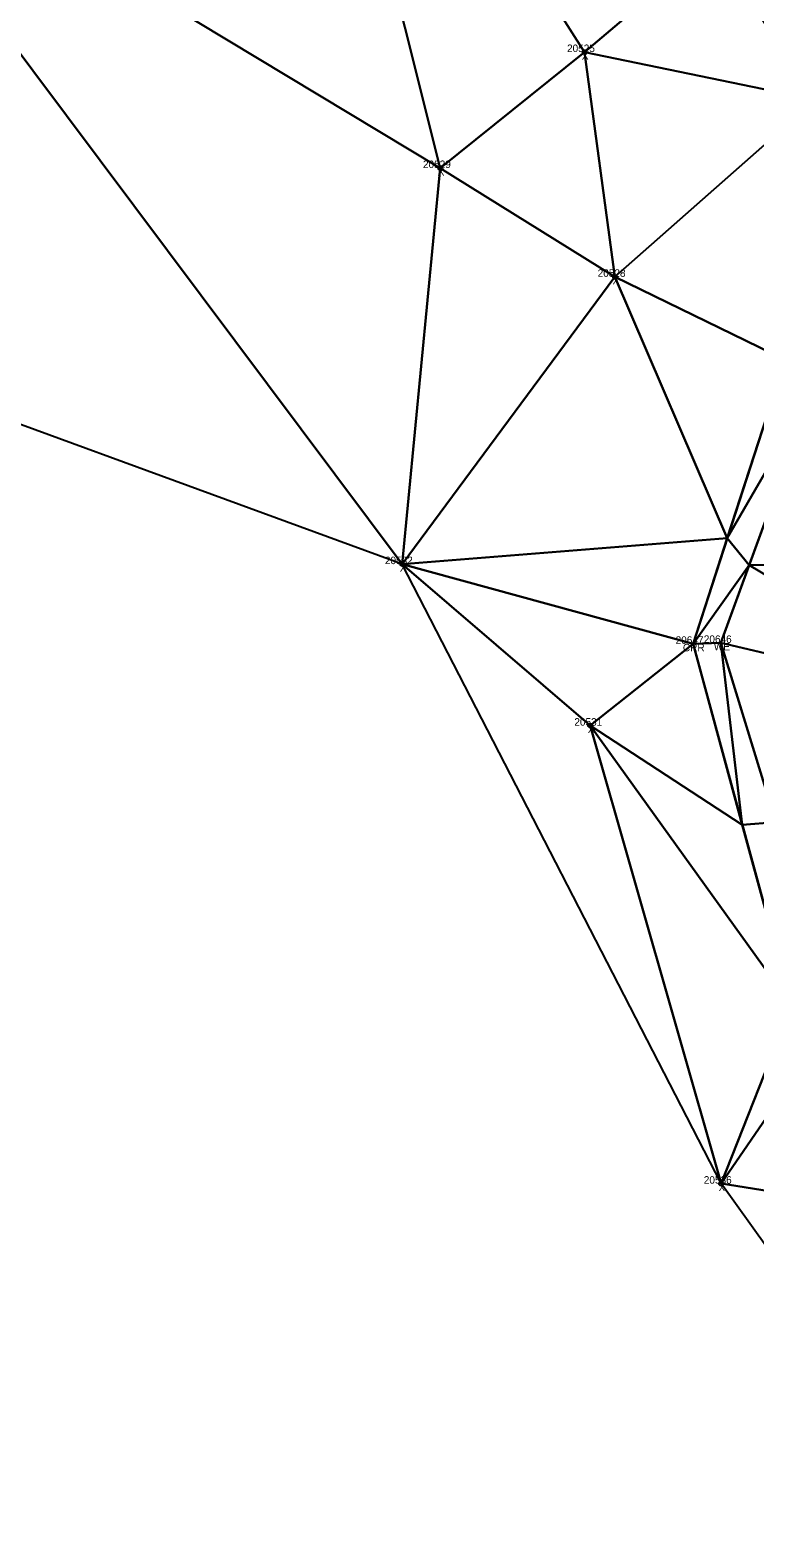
# Model space of a CAD drawing. Extents: x 1966740 to 1969291, y 1117379 to 1118460.
# Drawn here: x 1967626.6 to 1967723.3, y 1117454.2 to 1117655.1 of the extents above; entities that cross this region are included whole.
import ezdxf

# ---------------------------------------------------------------- set-up
doc = ezdxf.new("R2010")
doc.units = 0
for name, color, linetype in [('Level 10', 7, 'Continuous'), ('Level 30', 7, 'Continuous'), ('Level 35', 7, 'Continuous'), ('Level 50', 7, 'Continuous'), ('Level 52', 7, 'Continuous'), ('Level 60', 7, 'Continuous'), ('Level 61', 7, 'Continuous'), ('Level 62', 7, 'Continuous')]:
    doc.layers.add(name, color=color, linetype=linetype)

msp = doc.modelspace()

# ---------------------------------------------------------------- linework, layer by layer
at = {"layer": 'Level 10'}
for points in [[(1967849.83, 1118135.18), (1967825.91, 1118086.77), (1967802.99, 1118041.98), (1967795.15, 1117992.28), (1967793.27, 1117935.35), (1967800.64, 1117889.8), (1967800.4, 1117872.52), (1967800.8, 1117854.99), (1967811.67, 1117837.73), (1967837.15, 1117809.04), (1967808.01, 1117752.12), (1967788.48, 1117706.78), (1967783.36, 1117689.17), (1967764.63, 1117648.93), (1967738.42, 1117613.44), (1967731.11, 1117607.31), (1967718.77, 1117573.47), (1967736.01, 1117517.29), (1967781.71, 1117484.69), (1967799.34, 1117478.73), (1967814.43, 1117469.18)], [(1967794.3, 1117875.45), (1967796.63, 1117853.43), (1967809.67, 1117835.4), (1967828.83, 1117808.28), (1967805.08, 1117754.56), (1967786.33, 1117708.04), (1967780.19, 1117689.35), (1967762.68, 1117651.19), (1967736.39, 1117616.3), (1967727.33, 1117611.21), (1967715.04, 1117573.35), (1967731.01, 1117514.73), (1967775.86, 1117468.11), (1967793.29, 1117458.88), (1967816.39, 1117454.18)]]:
    msp.add_lwpolyline(points, dxfattribs=at)
at = {"layer": 'Level 30'}
for centre in [(1967700.55, 1117652.23), (1967681.31, 1117636.77), (1967704.63, 1117622.27), (1967676.25, 1117583.97), (1967701.31, 1117562.44), (1967718.78, 1117501.39)]:
    msp.add_circle(centre, 0.25, dxfattribs=at)
at = {"layer": 'Level 35'}
for points in [[(1967600.11, 1117685.65), (1967662.45, 1117711.98), (1967681.31, 1117636.77)], [(1967662.45, 1117711.98), (1967717.6, 1117666.66), (1967700.55, 1117652.23)], [(1967662.45, 1117711.98), (1967700.55, 1117652.23), (1967681.31, 1117636.77)], [(1967513.9, 1117643.33), (1967600.11, 1117685.65), (1967676.25, 1117583.97)], [(1967600.11, 1117685.65), (1967681.31, 1117636.77), (1967676.25, 1117583.97)], [(1967700.55, 1117652.23), (1967717.6, 1117666.66), (1967731.36, 1117645.86)], [(1967681.31, 1117636.77), (1967700.55, 1117652.23), (1967704.63, 1117622.27)], [(1967700.55, 1117652.23), (1967731.36, 1117645.86), (1967704.63, 1117622.27)], [(1967704.63, 1117622.27), (1967731.36, 1117645.86), (1967727.33, 1117611.21)], [(1967676.25, 1117583.97), (1967681.31, 1117636.77), (1967704.63, 1117622.27)], [(1967676.25, 1117583.97), (1967704.63, 1117622.27), (1967719.61, 1117587.44)], [(1967704.63, 1117622.27), (1967727.33, 1117611.21), (1967719.61, 1117587.44)], [(1967719.61, 1117587.44), (1967727.33, 1117611.21), (1967731.11, 1117607.31)], [(1967719.61, 1117587.44), (1967731.11, 1117607.31), (1967722.55, 1117583.83)], [(1967722.55, 1117583.83), (1967731.11, 1117607.31), (1967769.03, 1117583.97)], [(1967676.25, 1117583.97), (1967719.61, 1117587.44), (1967715.04, 1117573.35)], [(1967715.04, 1117573.35), (1967719.61, 1117587.44), (1967722.55, 1117583.83)], [(1967676.25, 1117583.97), (1967715.04, 1117573.35), (1967701.31, 1117562.44)], [(1967676.25, 1117583.97), (1967701.31, 1117562.44), (1967718.78, 1117501.39)], [(1967715.04, 1117573.35), (1967722.55, 1117583.83), (1967718.77, 1117573.47)], [(1967718.77, 1117573.47), (1967722.55, 1117583.83), (1967753.91, 1117565.22)], [(1967722.55, 1117583.83), (1967769.03, 1117583.97), (1967753.91, 1117565.22)], [(1967701.31, 1117562.44), (1967715.04, 1117573.35), (1967721.61, 1117549.24)], [(1967715.04, 1117573.35), (1967718.77, 1117573.47), (1967721.61, 1117549.24)], [(1967718.77, 1117573.47), (1967753.91, 1117565.22), (1967726.1, 1117549.57)], [(1967718.77, 1117573.47), (1967726.1, 1117549.57), (1967721.61, 1117549.24)], [(1967701.31, 1117562.44), (1967721.61, 1117549.24), (1967728.18, 1117525.13)], [(1967701.31, 1117562.44), (1967728.18, 1117525.13), (1967718.78, 1117501.39)], [(1967721.61, 1117549.24), (1967726.1, 1117549.57), (1967728.18, 1117525.13)], [(1967718.78, 1117501.39), (1967728.18, 1117525.13), (1967726.29, 1117512.34)], [(1967718.78, 1117501.39), (1967726.29, 1117512.34), (1967748.34, 1117496.72)], [(1967718.78, 1117501.39), (1967748.34, 1117496.72), (1967751.16, 1117456.25)]]:
    msp.add_lwpolyline(points, close=True, dxfattribs=at)
at = {"layer": 'Level 50'}
for centre in [(1967715.04, 1117573.35), (1967718.77, 1117573.47)]:
    msp.add_circle(centre, 0.001, dxfattribs=at)

# ---------------------------------------------------------------- texts
at = {"layer": 'Level 52'}
for s, p in [('20525', (1967698.23, 1117652.23)), ('20529', (1967679.01, 1117636.77)), ('20528', (1967702.32, 1117622.27)), ('20532', (1967673.93, 1117583.97)), ('20531', (1967699.21, 1117562.44)), ('20536', (1967716.48, 1117501.39))]:
    msp.add_text(s, height=1, dxfattribs=at).set_placement(p)
at = {"layer": 'Level 60'}
for s, p in [('CRR', (1967713.69, 1117572.35)), ('WE', (1967717.82, 1117572.47))]:
    msp.add_text(s, height=1, dxfattribs=at).set_placement(p)
at = {"layer": 'Level 61'}
for s, p in [('20647', (1967712.72, 1117573.35)), ('20646', (1967716.48, 1117573.47))]:
    msp.add_text(s, height=1, dxfattribs=at).set_placement(p)
at = {"layer": 'Level 62'}
for p in [(1967700.21, 1117651.23), (1967680.97, 1117635.77), (1967704.3, 1117621.27), (1967675.92, 1117582.97), (1967700.98, 1117561.44), (1967718.44, 1117500.39)]:
    msp.add_text('X', height=1, dxfattribs=at).set_placement(p)

doc.saveas('drawing.dxf')
